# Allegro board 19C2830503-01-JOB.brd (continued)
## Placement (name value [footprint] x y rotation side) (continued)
U35  TI_SN74AVC4T245PWR  [SOIC_16P_26_197X252]  30.1 47.37 0 top
U36  TI_PCA9306DCUT  [SOIC_8P_20_79X122]  38.35 45.97 0 bottom
U37  TI_SN74AVC4T245PWR  [SOIC_16P_26_197X252]  35.81 47.35 0 top
U38  TI_TPS51200DRCT  [QFN10P_20_118X118_TP94X65V5]  105.54 46.61 90 top
U39  SAMSUNG_K4B4G1646B-HCK0  [BGA_96P_31_524X394_C14]  46.1 42.1 270 top
U40  SAMSUNG_K4B4G1646B-HCK0  [BGA_96P_31_524X394_C14]  57.78 42.1 270 top
U41  SAMSUNG_K4B4G1646B-HCK0  [BGA_96P_31_524X394_C14]  69.42 42.1 270 top
U42  SAMSUNG_K4B4G1646B-HCK0  [BGA_96P_31_524X394_C14]  81.15 42.1 270 top
U43  SAMSUNG_K4B4G1646B-HCK0  [BGA_96P_31_524X394_C14]  92.84 42.1 270 top
U44  TI_UCD74120RVF  [QFN40P20_276X197T209X130V21]  130.56 35.94 270 top
U45  TI_SN74LVC244APWR  [SOIC_20P_26_256X252]  146.81 171.96 90 bottom
U46  ATMEL_AT93C46DN-SH-T  [SOIC_8P_50_193X236]  154.18 165.1 180 bottom
U47  MICROCHIP_MCP23S17T-E/SS  [SOIC_28P_26_402X307]  100.2 163.58 90 bottom
U48  MICROCHIP_MCP23S17T-E/SS  [SOIC_28P_26_402X307]  90.42 163.58 90 bottom
U49  TI_TS3L301DGG  [SOIC_48P_20_492X319]  140.72 155.96 270 bottom
U50  MICROCHIP_MCP23S17T-E/SS  [SOIC_28P_26_402X307]  106.17 153.16 90 bottom
U51  TI_SN74AVC4T245PWR  [SOIC_16P_26_197X252]  159.64 144.53 0 bottom
U52  TI_TXS0108EPWR  [SOIC_20P_26_256X252]  151.51 144.53 0 bottom
U53  MICROCHIP_MCP23S17T-E/SS  [SOIC_28P_26_402X307]  98.3 128.91 90 bottom
U54  TI_PCA9517DR  [SOIC_8P_50_193X236]  79.32 124.84 0 bottom
U55  TI_SN74LVC2G157DCUT  [SOIC_8P_20_79X122]  78.61 113.41 90 top
U56  TI_MAX3221ECPWR  [SOIC_16P_26_197X252]  156.21 114.81 180 bottom
U57  TI_SN74AVC4T245PWR  [SOIC_16P_26_197X252]  80.9 113.54 0 bottom
U58  TI_PCA9517DR  [SOIC_8P_50_193X236]  129.41 106.3 90 bottom
U59  TI_TPS2065CDBVR  [SOT-23_5P]  156.34 105.79 270 bottom
U60  TI_TPS51200DRCT  [QFN10P_20_118X118_TP94X65V5]  36.7 38.61 270 bottom
U61  TI_REF5025AID  [SOIC_8P_50_193X236]  131.93 74.88 180 top
U62  TI_SN74LVC1G32DCK  [SC70_5P]  99.31 122.17 270 bottom
U63  TI_SN74AUCH16244DGGR  [SOIC_48P_20_492X319]  36.93 131.01 90 bottom
U64  TI_SN74AUCH16244DGGR  [SOIC_48P_20_492X319]  36.93 144.27 90 bottom
U65  TI_SN74AUCH245RGYR  [QFN_20P_20_177X138_TP]  43.43 130.68 90 top
U67  TI_SN74AUC1G125DCKR  [SC70_5P]  40.94 147.88 180 top
U68  TI_SN74AUCH245RGYR  [QFN_20P_20_177X138_TP]  43.43 136.78 90 top
U69  TI_SN74LVC1G04DBVR  [SOT-23_5P]  50.7 162.38 0 bottom
U70  TI_SN74LVC1G07DCKR  [SC70_5P]  158.65 102.24 0 bottom
Y1  12MHz_20pF  [XTAL_2P_161_205X134_H59]  162.81 158.62 180 top
Y2  16MHz  [XTAL_2P_152_197X126]  161.26 134.16 0 top
Y3  25MHz_20pF  [XTAL_2P_161_205X134_H59]  147.45 87.44 0 bottom
Y4  25MHz_20pF  [XTAL_2P_161_205X134_H59]  150.5 63.81 0 bottom

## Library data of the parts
AMC1 = 00_GF-AMC-B_0
ATT PWR = 160_SW_4P_TSVB_0
B1-B8 B16 B17 B20 B27 B30 B32-B34 B38 B41 B43 B45 B46 B48 PB1 = 1212_BEAD_0
B9-B15 B23 B25 B31 B39 B44 B47 = 1212_FILTER_NFW31SP106X1E4L_0
B22 B24 = 1212_FILTER_0
B28 B29 = 1212_FILTER_NFM21P_0
C1-C6 C13 C17 C19 C21 C22 C24 C25 C27 C29 C34-C37 C40 C44 C45 C49 C55 C62 C67 C86 C87 C89 C92 C94 C95 C101 C102 C107 C114 C115 C117 C126-C130 C132 C133 C135 C136 C138 C139 C141 C142 C146 C147 C149 C152 C153 C155-C159 C161 C162 C164 C166 C167 C170 C171 C174-C180 C183 C184 C187 C189-C191 C193 C198-C200 C203-C205 C208 C210 C211 C215 C216 C218 C219 C224 C225 C227 C229 C230 C233-C235 C237 C238 C240 C241 C243 C245 C247 C248 C253 C257-C259 C262 C265 C267 C270 C272 C274 C276 C277 C282 C287 C288 C291 C296 C300-C303 C307-C309 C311 C312 C316-C319 C321 C323-C325 C331 C332 C334 C337 C338 C340-C342 C345 C347 C352-C356 C360-C362 C364 C366 C367 C371 C374 C378 C379 C382-C384 C388 C389 C392-C396 C398 C401 C402 C414 C416-C418 C421 C424 C427 C430 C434 C438-C440 C442-C450 C454-C457 C459 C460 C462-C475 C477-C483 C485-C496 C499-C502 C505-C507 C510-C513 C517 C521 C523 C525 C531 C538 C543 C555 C560 C561 C564 C566-C568 C571 C574 C577 C579 C580 C582 C588-C590 C592 C594 C596 C599 C601 C609 C613 C616 C619 C623 C626 C627 C630 C632 C636 C637 C641 C643 C646-C648 C658 C659 C661 C666 C668 C670-C672 C674 C675 C677 C679 C681 C682 C684 C686-C689 C695 C700 C702 C703 C710 C712 C715-C717 C720 C723 C725 C726 C730 C732 C734-C755 C758-C760 C763 C768-C772 C774 C776 C777 C782 C783 C788 C790 C793 = 11_C_0: signal model: DEFAULT_CAPACITOR_100000pF_2_1
C7 C8 C11 C12 C15 C23 C30 C31 C108 C113 C143 C144 C148 C150 C151 C169 C207 C249 C315 C333 C336 C339 C343 C346 C349 C372 C376 C385 C386 C397 C413 C578 C591 C654 C669 C778 C787 = 11_C_0: signal model: DEFAULT_CAPACITOR_1e+07pF_2_1
C9 = 11_C_0: signal model: DEFAULT_CAPACITOR_1200pF_2_1
C10 C16 C20 C26 C54 C69 C72 C73 C77 C78 C80 C85 C90 C99 C120-C122 C131 C192 C195 C201 C202 C206 C209 C214 C217 C220 C246 C255 C260 C263 C268 C273 C278 C290 C294 C363 C391 C514 C520 C522 C526 C527 C529 C542 C545-C547 C549 C550 C558 C559 C565 C572 C581 C584 C585 C602 C603 C606-C608 C610-C612 C615 C620 C622 C628 C631 C635 C639 C640 C644 C650-C653 C662 C663 C667 C673 C676 C678 C685 C698 C701 C705 C707 C709 C713 C714 C756 C757 C761 C764 C766 C784 C794 = 11_C_0: signal model: DEFAULT_CAPACITOR_10000pF_2_1
C14 = 11_C_0: signal model: DEFAULT_CAPACITOR_8200pF_2_1
C18 C81-C84 C116 C236 C239 C244 C252 C350 C461 C515 C516 C518 C519 C530 C533 C535 C539-C541 C548 C552-C554 C556 C562 C563 C573 C575 C583 C586 C587 C597 C598 C600 C604 C605 C617 C621 C624 C629 C633 C634 C638 C645 C649 C655 C657 C660 C664 C665 C680 C683 C690-C694 C696 C697 C699 C704 C706 C711 = 11_C_0: signal model: DEFAULT_CAPACITOR_560pF_2_1
C28 C33 = 11_C_0: signal model: DEFAULT_CAPACITOR_33pF_2_1
C32 = 11_C_0: signal model: DEFAULT_CAPACITOR_8.2pF_2_1
C38 C42 C100 C160 C228 C344 C415 C625 C733 C792 = 11_C_0: signal model: DEFAULT_CAPACITOR_2.2e+06pF_2_1
C39 C831-C834 = 11_C_POLAR_0
C41 C173 = 11_C_POLAR_0: signal model: DEFAULT_CAPACITOR_1e+08pF_2_1
C43 C48 C242 C256 C264 C289 C299 C306 C381 C425 C426 C504 C537 C780 C781 C785 C786 C789 = 11_C_0: signal model: DEFAULT_CAPACITOR_2.2e+07pF_2_1
C46 C47 C52 C53 C56 C59 C64 C68 C97 C98 C110 C111 C196 C197 C222 C223 C313 C365 C373 C377 C419 C422 C451 C452 C509 C576 C595 C614 C656 C721 C762 C773 C779 = 11_C_0: signal model: DEFAULT_CAPACITOR_4.7e+07pF_2_1
C50 C51 C60 C63 C182 C221 C292 C791 = 11_C_0: signal model: DEFAULT_CAPACITOR_220000pF_2_1
C57 C76 C104 C105 C185 C188 C194 C212 C213 C226 C254 C261 C271 C293 C295 C297 C328 C409 C420 C429 C441 C508 C557 C593 C618 C767 = 11_C_0: signal model: DEFAULT_CAPACITOR_4.7e+06pF_2_1
C58 C79 C109 C186 C269 C279-C281 C348 C370 C453 C458 C528 C536 C708 C722 = 11_C_0: signal model: DEFAULT_CAPACITOR_1000pF_2_1
C61 C74 C88 C91 C93 C96 C103 C106 C134 C137 C165 C168 C181 C232 C250 C266 C275 C285 C304 C305 C314 C322 C329 C330 C335 C351 C357-C359 C410-C412 C423 C476 C484 C724 C729 C731 C775 = 11_C_0: signal model: DEFAULT_CAPACITOR_1e+06pF_2_1
C65 C75 C327 C380 C432 C435-C437 C503 C544 C728 C795 = 11_C_POLAR_0: signal model: DEFAULT_CAPACITOR_4.7e+08pF_2_1
C66 C326 C368 C390 C399 C400 C433 C498 C532 C551 C642 C727 C765 = 11_C_0: signal model: DEFAULT_CAPACITOR_1e+08pF_2_1
C70 C71 = 11_C_0: signal model: DEFAULT_CAPACITOR_10pF_2_1
C112 C140 C163 C497 = 11_C_0: signal model: DEFAULT_CAPACITOR_100pF_2_1
C118 = 11_C_0: signal model: DEFAULT_CAPACITOR_470pF_2_1
C119 C124 C125 C145 C231 C251 C283 C284 C524 C534 = 11_C_0: signal model: 11_C_0_C0402_DISCRETE_NL/0.1UF_NL/0.1uF
C123 C172 = 11_C_0: signal model: DEFAULT_CAPACITOR_22000pF_2_1
C369 C403 C796-C823 C825-C830 C835-C844 = 11_C_0
C375 = 11_C_0: signal model: DEFAULT_CAPACITOR_1.5pF_2_1
C387 = 11_C_0: signal model: DEFAULT_CAPACITOR_56pF_2_1
C404-C408 = 11_C_0: signal model: DEFAULT_CAPACITOR_470000pF_2_1
C428 C431 = 11_C_POLAR_0: signal model: DEFAULT_CAPACITOR_4.7e+07pF_2_1
C569 C570 C718 C719 = 11_C_0: signal model: DEFAULT_CAPACITOR_27pF_2_1
CN1 = 1654_PWR_2P_5223957-3_0
CN2 CN8 = 1653_JH3X1V-2M_0
CN3 = 1654_BB_60X2P_4HOLD_QSH_0
CN4-CN6 CN10 CN23 = 1654_HS_UFL-R-SMT-1_0
CN7 = 1653_JH6X1V-2M_0
CN9 CN15 CN24 = 1653_HD_2P_D_0
CN11-CN13 = 1654_COAXIAL_4P_MM8030_0
CN16 = 1652_RJ45_28P_RTB-19GB9J1A_0
CN17 = 1653_JH4X2V_0
CN18 = 1654_RF-SMAC037_0
CN19 CN20 = 1653_HD_4X1P_222-96_0
CN21 = 1653_JH3X1V-51462803_0
CN22 = 1653_HD_5X2P_0
D1 = 130_TVS_SON6_TPD4S012DRY_0
D3 = 130_LED_2P_R_KPA-1606EC_0
D4 = 130_LED_LED-0603_G_0
D5 DBG_D2 DBG_D3 = 130_LED_2P_B_KPA-1606QBC-D_0
D6 = 130_LED_LED-0603_R_0
D7 = 130_SCHOTTKY_0
D8 = 130_ZENER_SOT-23A_13_1
D9 D11 = 130_SCHOTTKY_ANODE2_0
D10 = 130_SCHOTTKY_0805_0
D14 = 130_TVS_SOT_TPD2EUSB30DRT_0
DBG_D1 = 130_LED_3P_KPBA-3010ESGC_0
DC_IN1 = 12_DCJACK_3P_2DC-0005B100_0
DIMM1 = 1651_DDR3-SODIMM_204P_DDRSK_E_0
EEPROM1 = 141_ST_M24M01-HRMN6TP_0
EMU1 = 1654_BB_30X2P_2HOLD_QSH_0
ESD1 = 00_AMC-ESD-B_0
FAN1 = 12_WF_4P_BOX_D_0
FM1-FM4 = 00_Fiducial_0
FTDI_USB = 1654_USB-UH51543_MABTYPE_0
GPS1 = 141_GNS_TC6000G_1
H1 H2 = 00_H35P7-MTH_0
H7 = 00_SCREWHOLE_OVAL_NPTH_0
H8 = 00_H27P35-MTH_0
J1 = 1654_ATCA_160P_J30_1
J2 = 1654_ATCA_160P_J31_1
L1 = 1211_L_0: signal model: DEFAULT_INDUCTOR_22000nH_2_1
L2 L8 = 1211_CHOKE_0: signal model: DEFAULT_INDUCTOR_3300nH_2_1
L3 L5-L7 L12 = 1211_CHOKE_0: signal model: DEFAULT_INDUCTOR_470nH_2_1
L4 = 1211_CHOKE_0: signal model: DEFAULT_INDUCTOR_200nH_2_1
L9 = 1211_L_0: signal model: DEFAULT_INDUCTOR_1800nH_2_1
L10 = 09_L_0: signal model: DEFAULT_INDUCTOR_82nH_2_1
L11 = 1211_L_0: signal model: DEFAULT_INDUCTOR_3.6nH_2_1
LCD1 = 968_LCD_17P_NHD-C12832A1Z_0
MCU SOC = 12_WF_4P_D_744-81-04TW20_0
NAND1 = 141_MICRON_MT29F4G08ABBDAHCIT_0
NOR1 = 141_NUMONYX_N25Q128A11BSF40F_0
OSC1 OSC4 = 1233_OSC_4P_0
OSC2 = 1233_OSC_6P_0
OSC3 = 1233_OSC_4P_M6049LF_0
PHY1 PHY2 = 141_MARVELL_88E1111-B1-BAB_0
PMBUS1 = 1653_JH5X1V_0
Q1 Q7 Q8 = 141_TI_TPS73701DRBT_0
Q2 = 141_TI_TPS74701_0
Q3-Q5 Q9 Q11 Q12 Q14 Q16 Q18 = 131_SOT-23A_BEC_0
Q6 Q15 Q17 Q21 = 141_MICROCHIP_MCP9700AT-E-LT_0
Q10 = 131_REG_SOT-223_TLV1117_0
Q13 = 131_REG_SOT-23_APL431LBAI_0
Q19 = 131_SOIC8_SGDP_0
Q20 = 131_N_MOS_SOT-23_1
R1 R2 = 10_R_0: signal model: DEFAULT_RESISTOR_0.01OHM_2_1
R3 R65 R77 R198 R216 R261 R267 R320 R328 R346 R397 R419 R435 R441 R442 R472 R567 R769 R770 R783 = 10_R_0: signal model: DEFAULT_RESISTOR_1000OHM_2_1
R4 R7 R11 R14 R20 R21 R24 R28 R40 R59 R81-R83 R92 R93 R121 R122 R174-R176 R214 R222 R228 R248 R249 R251 R255 R270 R274 R275 R281 R292 R297 R300 R304 R306 R307 R318 R321 R329 R377 R386 R395 R404-R407 R411-R418 R422 R429 R430 R446-R453 R460 R461 R479 R484 R495-R498 R505 R528 R540 R544 R546 R581 R603 R604 R610 R612 R616 R617 R623 R639 R652 R679 R735 R750 R762 R773 R780 R785 R787 R791 R793 = 10_R_0: signal model: DEFAULT_RESISTOR_10000OHM_2_1
R5 R6 R147-R150 R171 R196 R237 R260 R276 R279 R287 R308 R319 R322 R326 R343 R347 R365 R410 R432 R487-R489 R502 R503 R549 R568 R585 R601 R643 R677 R686 R687 R726 R798-R817 = 10_R_0
R8 = 10_R_0: signal model: DEFAULT_RESISTOR_82500OHM_2_1
R9 R18 R26 R35 R39 R41 R45 R46 R51 R52 R54 R75 R86 R98 R116 R117 R123 R129-R131 R145 R162-R166 R178-R185 R188-R190 R192 R193 R200 R203 R204 R206 R210 R215 R223 R225 R226 R231 R234 R235 R238 R242-R247 R250 R252 R253 R262-R265 R268 R269 R277 R280 R285 R301 R305 R323 R325 R338 R351 R354 R378 R380 R433 R468 R471 R514 R515 R524 R531 R536 R541 R547 R555 R560 R563 R564 R566 R579 R580 R589 R607 R608 R613 R622 R642 R644-R647 R653-R655 R658 R660 R669 R725 R727-R730 R736-R738 R742 R755 R759 R764 R774 = 10_R_0: signal model: DEFAULT_RESISTOR_0.001OHM_2_1
R10 = 10_R_0: signal model: DEFAULT_RESISTOR_1870OHM_2_1
R12 R27 R100 R309 R369 R372 R373 R423 R480 R490 R609 R621 R628 R690-R692 = 10_R_0: signal model: DEFAULT_RESISTOR_22OHM_2_1
R13 = 10_R_0: signal model: DEFAULT_RESISTOR_31600OHM_2_1
R15 = 10_R_0: signal model: DEFAULT_RESISTOR_56200OHM_2_1
R16 R25 R29 R34 R36 R38 R42 R48 R50 R56 R69 R220 R224 R232 R271 R289-R291 R312 R313 R324 R330-R332 R334 R336 R337 R339-R341 R344 R359 R362 R363 R366 R379 R381 R385 R389 R390 R394 R408 R421 R425 R426 R428 R438 R439 R470 R477 R521 R530 R557 R569-R573 R575-R578 R587 R590-R600 R620 R625 R629 R631 R648 R650 R651 R661-R666 R672-R676 R688 R696 R701 R702 R706 R707 R709 R711 R713 R714 R720 R721 R723 R731 R733 R734 R739 R744-R749 R751-R754 R758 R796 R797 = 10_R_0: signal model: DEFAULT_RESISTOR_4700OHM_2_1
R17 R105 R128 R456 R699 = 10_R_0: signal model: DEFAULT_RESISTOR_22600OHM_2_1
R19 = 10_R_0: signal model: DEFAULT_RESISTOR_17400OHM_2_1
R22 = 10_R_0: signal model: DEFAULT_RESISTOR_1690OHM_2_1
R23 = 10_R_0: signal model: DEFAULT_RESISTOR_3570OHM_2_1
R30 R70 R111 R492 R534 = 10_R_0: signal model: DEFAULT_RESISTOR_330OHM_2_1
R31 R76 R219 R299 R494 R504 R510 R522 R525 R533 = 10_R_0: signal model: DEFAULT_RESISTOR_510OHM_2_1
R32 R239 R240 R256 R257 R272 R273 R618 R624 R626 R630 R633 R636 R637 R641 R680 R681 R689 R695 R700 R705 R710 R717 = 10_R_0: signal model: DEFAULT_RESISTOR_49.9OHM_2_1
R33 R91 R146 R152 R170 R195 R201 R229 R233 R282 R288 R295 R370 R473-R476 R682 R683 R693 = 10_R_0: signal model: DEFAULT_RESISTOR_100OHM_2_1
R37 R43 R44 R47 R49 R53 R55 R57 R60 R62-R64 R66-R68 R71-R73 R78-R80 R87 R89 R90 R94 R96 R97 R103 R104 R109 R110 R157 R158 R293 R294 R311 R314-R316 R348 R352 R355 R357 R364 R367 R368 R374 R383 R384 R387 R388 R391 R393 R396 R398 R401 R402 R507 R516 R520 R523 R527 R529 R532 R535 R539 R542 R558 R605 R606 R614 R615 R619 R668 R670 R697 R703 R708 R712 R718 R722 R724 R732 R740 R741 R743 R756 R757 = 10_R_0: signal model: DEFAULT_RESISTOR_10OHM_2_1
R58 R61 R112 R511 R517 R519 = 10_R_0: signal model: DEFAULT_RESISTOR_4750OHM_2_1
R84 R161 R217 = 10_R_0: signal model: DEFAULT_RESISTOR_8200OHM_2_1
R85 R106 R173 R191 R197 R358 R399 R400 R420 R424 R469 R582 R583 = 10_R_0: signal model: DEFAULT_RESISTOR_2000OHM_2_1
R113 R136 R768 = 10_R_0: signal model: DEFAULT_RESISTOR_8060OHM_2_1
R114 R115 R134 R135 R766 R767 = 10_R_0: signal model: DEFAULT_RESISTOR_2490OHM_2_1
R137-R140 R342 R345 R349 R356 = 10_R_0: signal model: DEFAULT_RESISTOR_750OHM_2_1
R151 R172 R317 R403 R409 R427 R431 R434 R436 R437 R440 R586 R611 = 10_R_0: signal model: DEFAULT_RESISTOR_100000OHM_2_1
R159 R202 R588 R602 R627 R634 R659 R678 R694 R704 R715 = 10_R_0: signal model: DEFAULT_RESISTOR_4990OHM_2_1
R207 R213 = 10_R_0: signal model: DEFAULT_RESISTOR_1OHM_2_1
R208 R375 = 10_R_0: signal model: DEFAULT_RESISTOR_10200OHM_2_1
R209 R376 = 10_R_0: signal model: DEFAULT_RESISTOR_1500OHM_2_1
R212 R218 = 10_R_0: signal model: DEFAULT_RESISTOR_90900OHM_2_1
R221 R227 = 10_R_0: signal model: DEFAULT_RESISTOR_560OHM_2_1
R241 R259 R303 = 10_R_0: signal model: DEFAULT_RESISTOR_3160OHM_2_1
R258 R302 R584 = 10_R_0: signal model: DEFAULT_RESISTOR_5600OHM_2_1
R278 R286 R574 = 10_R_0: signal model: DEFAULT_RESISTOR_33OHM_2_1
R283 = 10_R_0: signal model: DEFAULT_RESISTOR_39200OHM_2_1
R284 = 10_R_0: signal model: DEFAULT_RESISTOR_36500OHM_2_1
R296 R538 R551 R761 = 10_R_0: signal model: DEFAULT_RESISTOR_1300OHM_2_1
R298 = 10_R_0: signal model: DEFAULT_RESISTOR_475OHM_2_1
R310 R632 R635 R638 R649 R656 R667 R671 R685 R698 = 10_R_0: signal model: DEFAULT_RESISTOR_3000OHM_2_1
R327 R333 R335 R350 R371 R382 = 10_R_0: signal model: DEFAULT_RESISTOR_220OHM_2_1
R353 = 10_R_0: signal model: DEFAULT_RESISTOR_698OHM_2_1
R360 R361 = 10_R_0: signal model: DEFAULT_RESISTOR_75000OHM_2_1
R443-R445 R454 R455 R457 R458 R462-R467 R763 R765 R772 R775 R779 R781 R782 R786 R788-R790 R792 R794 R795 = 10_R_0: signal model: DEFAULT_RESISTOR_39.2OHM_2_1
R459 R537 R550 = 10_R_0: signal model: DEFAULT_RESISTOR_2OHM_2_1
R481 = 10_R_0: signal model: DEFAULT_RESISTOR_2870OHM_2_1
R482 = 10_R_0: signal model: DEFAULT_RESISTOR_2200OHM_2_1
R483 = 10_R_0: signal model: DEFAULT_RESISTOR_12100OHM_2_1
R485 R491 R493 R506 R513 = 10_R_0: signal model: DEFAULT_RESISTOR_27OHM_2_1
R499-R501 = 10_R_0: signal model: DEFAULT_RESISTOR_3300OHM_2_1
R508 = 10_R_0: signal model: DEFAULT_RESISTOR_6980OHM_2_1
R509 = 10_R_0: signal model: DEFAULT_RESISTOR_12OHM_2_1
R512 = 10_R_0: signal model: DEFAULT_RESISTOR_200OHM_2_1
R518 R526 = 10_R_0: signal model: DEFAULT_RESISTOR_33000OHM_2_1
R545 R553 R760 = 10_R_0: signal model: DEFAULT_RESISTOR_931OHM_2_1
R640 R684 R719 R771 R776-R778 R784 RR1 = 10_R_0: signal model: DEFAULT_RESISTOR_240OHM_2_1
R657 R716 = 10_R_0: signal model: DEFAULT_RESISTOR_45.3OHM_2_1
RST_MCU1 = 160_SW_2P_PT-004-E1_0
SIM1 = 1654_SIMCARD_8P_FMS006Z-2001_0
SOC_USB = 1654_USB3-A_9P_UEA1112C-4HK1_0
SOCKET1 = 00_TI_SOC_K2H_Socket_0
SW1 = 160_SW_8P_ESD104EZ_0
TP1 TP6 TP10 TP59 = 00_TP-S40_0
TP2-TP5 TP7-TP9 TP11-TP58 TP60-TP62 TP64-TP97 = 00_TP28_0
U1 U2 = 141_TI_TPS54620RGY_0
U3 = 141_FTDI_FT2232HL_0
U4 U28 = 14S_SN74LVC2G125DCUR_US-8_1
U5 U52 = 141_TI_TXS0108EPWR_0
U6 = 141_TI_SN74AHCT1G08DCKT_0
U7 = 14_TI_LM3S2D93-IQC80_0
U8 = 141_TI_UCD74111_0
U9 U23 = 141_TI_UCD7242RSJT_0
U10 U44 = 141_TI_UCD74120_0
U11 U62 = 141_TI_SN74LVC1G32_0
U12 U17 U21 U30 U55 = 141_TI_SN74LVC2G157_0
U13 = 141_TI_UCD9090_0
U14 U15 U19 = 141_TI_CDCM6208_1
U16 U25 = 141_TI_UCD9244RGCR_1
U18 U56 = 141_TI_MAX3221E_0
U20 = 141_IDT_5V41068A_0
U22 U34 U54 U58 = 141_TI_PCA9517DR_0
U24 = 14_TI_TMS320TCI6638_4
U26 = 141_TI_SN74LVC1G19DCKR_0
U27 = 141_TI_UCD74106_0
U29 = 141_TI_DAC8550_0
U31 U36 = 141_TI_PCA9306DCUT_0
U32 U35 U37 U51 U57 = 141_TI_SN74AVC4T245PWR_0
U33 = 141_TI_TXS4555RGTR_0
U38 U60 = 141_TI_TPS51200DRCT_0
U39-U43 = 141_SAMSUNG_K4B4G1646B-HCK0_0
U45 = 14S_74LVC244_TSSOP20-S_1
U46 = 141_ATMEL_AT93C46DN-SH-T_0
U47 U48 U50 U53 = 141_MCP23S17T_SSOP28-209MIL_0
U49 = 141_TI_TS3L301DGG_1
U59 = 141_TI_TPS2065CDBVR_1
U61 = 141_TI_REF5050AIDR_0
U63 U64 = 141_SN74AUCH16244DGGR_TSSOP48_0
U65 U68 = 141_TI_SN74AUCH245RGYR_0
U67 = 141_TI_SN74AUC1G125DCKR_0
U69 = 141_TI_SN74LVC1G04DBVR_0
U70 = 141_TI_SN74LVC1G07DCKR_0
Y1-Y4 = 1231_XTAL_2P_0

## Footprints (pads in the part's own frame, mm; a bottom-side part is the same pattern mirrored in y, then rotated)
ACM2012
  rect 0.762x0.406 smd: 1(-0.925,0.4) 2(-0.925,-0.4) 3(0.925,-0.4) 4(0.925,0.4)
AMC-ESD-B
  custom 1.175x1.175 smd: 1(0,-0.3)
  custom 0.25x0.25 smd: 2(-125.5,1.55) 3(-138.5,1.55)
  round 3.2 hole 2.692: 4(0,0)
ATCA_160P_384312
  rect 0.864x0.864 hole 0.457: A1(11.25,1.1)
  round 0.864 hole 0.457: A2(8.75,1.1) A3(6.25,1.1) A4(3.75,1.1) A5(1.25,1.1) A6(-1.25,1.1) A7(-3.75,1.1) A8(-6.25,1.1) A9(-8.75,1.1) A10(-11.25,1.1) B1(11.25,2.3) B2(8.75,2.3) B3(6.25,2.3) B4(3.75,2.3) B5(1.25,2.3) B6(-1.25,2.3) B7(-3.75,2.3) B8(-6.25,2.3) B9(-8.75,2.3) B10(-11.25,2.3) C1(11.25,5.6) C2(8.75,5.6) C3(6.25,5.6) C4(3.75,5.6) C5(1.25,5.6) C6(-1.25,5.6) C7(-3.75,5.6) C8(-6.25,5.6) C9(-8.75,5.6) C10(-11.25,5.6) D1(11.25,6.8) D2(8.75,6.8) D3(6.25,6.8) D4(3.75,6.8) D5(1.25,6.8) D6(-1.25,6.8) D7(-3.75,6.8) D8(-6.25,6.8) D9(-8.75,6.8) D10(-11.25,6.8) E1(11.25,10.1) E2(8.75,10.1) E3(6.25,10.1) E4(3.75,10.1) E5(1.25,10.1) E6(-1.25,10.1) E7(-3.75,10.1) E8(-6.25,10.1) E9(-8.75,10.1) E10(-11.25,10.1) F1(11.25,11.3) F2(8.75,11.3) F3(6.25,11.3) F4(3.75,11.3) F5(1.25,11.3) F6(-1.25,11.3) F7(-3.75,11.3) F8(-6.25,11.3) F9(-8.75,11.3) F10(-11.25,11.3) G1(11.25,14.6) G2(8.75,14.6) G3(6.25,14.6) G4(3.75,14.6) G5(1.25,14.6) G6(-1.25,14.6) G7(-3.75,14.6) G8(-6.25,14.6) G9(-8.75,14.6) G10(-11.25,14.6) GA1(10.21,0) GA2(7.71,0) GA3(5.21,0) GA4(2.71,0) GA5(0.21,0) GA6(-2.29,0) GA7(-4.79,0) GA8(-7.29,0) GA9(-9.79,0) GA10(-12.29,0) GH1(11.25,17) GH2(8.75,17) GH3(6.25,17) GH4(3.75,17) GH5(1.25,17) GH6(-1.25,17) GH7(-3.75,17) GH8(-6.25,17) GH9(-8.75,17) GH10(-11.25,17) H1(11.25,15.8) H2(8.75,15.8) H3(6.25,15.8) H4(3.75,15.8) H5(1.25,15.8) H6(-1.25,15.8) H7(-3.75,15.8) H8(-6.25,15.8) H9(-8.75,15.8) H10(-11.25,15.8)
  round 0.711 hole 0.457: GB1(11.25,3.5) GB2(8.75,3.5) GB3(6.25,3.5) GB4(3.75,3.5) GB5(1.25,3.5) GB6(-1.25,3.5) GB7(-3.75,3.5) GB8(-6.25,3.5) GB9(-8.75,3.5) GB10(-11.25,3.5) GC1(11.25,4.4) GC2(8.75,4.4) GC3(6.25,4.4) GC4(3.75,4.4) GC5(1.25,4.4) GC6(-1.25,4.4) GC7(-3.75,4.4) GC8(-6.25,4.4) GC9(-8.75,4.4) GC10(-11.25,4.4) GD1(11.25,8) GD2(8.75,8) GD3(6.25,8) GD4(3.75,8) GD5(1.25,8) GD6(-1.25,8) GD7(-3.75,8) GD8(-6.25,8) GD9(-8.75,8) GD10(-11.25,8) GE1(11.25,8.9) GE2(8.75,8.9) GE3(6.25,8.9) GE4(3.75,8.9) GE5(1.25,8.9) GE6(-1.25,8.9) GE7(-3.75,8.9) GE8(-6.25,8.9) GE9(-8.75,8.9) GE10(-11.25,8.9) GF1(11.25,12.5) GF2(8.75,12.5) GF3(6.25,12.5) GF4(3.75,12.5) GF5(1.25,12.5) GF6(-1.25,12.5) GF7(-3.75,12.5) GF8(-6.25,12.5) GF9(-8.75,12.5) GF10(-11.25,12.5) GG1(11.25,13.4) GG2(8.75,13.4) GG3(6.25,13.4) GG4(3.75,13.4) GG5(1.25,13.4) GG6(-1.25,13.4) GG7(-3.75,13.4) GG8(-6.25,13.4) GG9(-8.75,13.4) GG10(-11.25,13.4)
BB_30X2P_20_838X285_F
  round 1.016 hole 1.016 unplated: (-10.065,2.67) (10.065,2.67)
  oval 0.279x2.286 smd: 1(-7.25,-2.87) 2(-7.25,2.87) 3(-6.75,-2.87) 4(-6.75,2.87) 5(-6.25,-2.87) 6(-6.25,2.87) 7(-5.75,-2.87) 8(-5.75,2.87) 9(-5.25,-2.87) 10(-5.25,2.87) 11(-4.75,-2.87) 12(-4.75,2.87) 13(-4.25,-2.87) 14(-4.25,2.87) 15(-3.75,-2.87) 16(-3.75,2.87) 17(-3.25,-2.87) 18(-3.25,2.87) 19(-2.75,-2.87) 20(-2.75,2.87) 21(-2.25,-2.87) 22(-2.25,2.87) 23(-1.75,-2.87) 24(-1.75,2.87) 25(-1.25,-2.87) 26(-1.25,2.87) 27(-0.75,-2.87) 28(-0.75,2.87) 29(-0.25,-2.87) 30(-0.25,2.87) 31(0.25,-2.87) 32(0.25,2.87) 33(0.75,-2.87) 34(0.75,2.87) 35(1.25,-2.87) 36(1.25,2.87) 37(1.75,-2.87) 38(1.75,2.87) 39(2.25,-2.87) 40(2.25,2.87) 41(2.75,-2.87) 42(2.75,2.87) 43(3.25,-2.87) 44(3.25,2.87) 45(3.75,-2.87) 46(3.75,2.87) 47(4.25,-2.87) 48(4.25,2.87) 49(4.75,-2.87) 50(4.75,2.87) 51(5.25,-2.87) 52(5.25,2.87) 53(5.75,-2.87) 54(5.75,2.87) 55(6.25,-2.87) 56(6.25,2.87) 57(6.75,-2.87) 58(6.75,2.87) 59(7.25,-2.87) 60(7.25,2.87)
  rect 4.699x0.635 smd: H3(-3.175,0) H4(3.175,0)
  rect 2.54x0.635 smd: H5(8.065,0) H6(-8.065,0)
BB_60X2P_20_2225X285_F
  round 1.016 hole 1.016 unplated: (-20.065,2.67) (20.065,2.67)
  oval 0.279x2.286 smd: 1(-17.25,-2.87) 2(-17.25,2.87) 3(-16.75,-2.87) 4(-16.75,2.87) 5(-16.25,-2.87) 6(-16.25,2.87) 7(-15.75,-2.87) 8(-15.75,2.87) 9(-15.25,-2.87) 10(-15.25,2.87) 11(-14.75,-2.87) 12(-14.75,2.87) 13(-14.25,-2.87) 14(-14.25,2.87) 15(-13.75,-2.87) 16(-13.75,2.87) 17(-13.25,-2.87) 18(-13.25,2.87) 19(-12.75,-2.87) 20(-12.75,2.87) 21(-12.25,-2.87) 22(-12.25,2.87) 23(-11.75,-2.87) 24(-11.75,2.87) 25(-11.25,-2.87) 26(-11.25,2.87) 27(-10.75,-2.87) 28(-10.75,2.87) 29(-10.25,-2.87) 30(-10.25,2.87) 31(-9.75,-2.87) 32(-9.75,2.87) 33(-9.25,-2.87) 34(-9.25,2.87) 35(-8.75,-2.87) 36(-8.75,2.87) 37(-8.25,-2.87) 38(-8.25,2.87) 39(-7.75,-2.87) 40(-7.75,2.87) 41(-7.25,-2.87) 42(-7.25,2.87) 43(-6.75,-2.87) 44(-6.75,2.87) 45(-6.25,-2.87) 46(-6.25,2.87) 47(-5.75,-2.87) 48(-5.75,2.87) 49(-5.25,-2.87) 50(-5.25,2.87) 51(-4.75,-2.87) 52(-4.75,2.87) 53(-4.25,-2.87) 54(-4.25,2.87) 55(-3.75,-2.87) 56(-3.75,2.87) 57(-3.25,-2.87) 58(-3.25,2.87) 59(-2.75,-2.87) 60(-2.75,2.87) 61(2.75,-2.87) 62(2.75,2.87) 63(3.25,-2.87) 64(3.25,2.87) 65(3.75,-2.87) 66(3.75,2.87) 67(4.25,-2.87) 68(4.25,2.87) 69(4.75,-2.87) 70(4.75,2.87) 71(5.25,-2.87) 72(5.25,2.87) 73(5.75,-2.87) 74(5.75,2.87) 75(6.25,-2.87) 76(6.25,2.87) 77(6.75,-2.87) 78(6.75,2.87) 79(7.25,-2.87) 80(7.25,2.87) 81(7.75,-2.87) 82(7.75,2.87) 83(8.25,-2.87) 84(8.25,2.87) 85(8.75,-2.87) 86(8.75,2.87) 87(9.25,-2.87) 88(9.25,2.87) 89(9.75,-2.87) 90(9.75,2.87) 91(10.25,-2.87) 92(10.25,2.87) 93(10.75,-2.87) 94(10.75,2.87) 95(11.25,-2.87) 96(11.25,2.87) 97(11.75,-2.87) 98(11.75,2.87) 99(12.25,-2.87) 100(12.25,2.87) 101(12.75,-2.87) 102(12.75,2.87) 103(13.25,-2.87) 104(13.25,2.87) 105(13.75,-2.87) 106(13.75,2.87) 107(14.25,-2.87) 108(14.25,2.87) 109(14.75,-2.87) 110(14.75,2.87) 111(15.25,-2.87) 112(15.25,2.87) 113(15.75,-2.87) 114(15.75,2.87) 115(16.25,-2.87) 116(16.25,2.87) 117(16.75,-2.87) 118(16.75,2.87) 119(17.25,-2.87) 120(17.25,2.87)
  rect 4.699x0.635 smd: H3(-13.175,0) H4(-6.825,0) H7(6.825,0) H8(13.175,0)
  rect 2.54x0.635 smd: H5(-1.935,0) H6(-18.065,0) H9(18.065,0) H10(1.935,0)
  round 6.35 hole 3.962: H11(-24.33,0) H12(24.33,0)
BGA_36P_60_394X366
  round 0.508 smd: A1(-3.75,-3.75) A2(-2.25,-3.75) A3(-0.75,-3.75) A4(0.75,-3.75) A5(2.25,-3.75) A6(3.75,-3.75) B1(-3.75,-2.25) B2(-2.25,-2.25) B3(-0.75,-2.25) B4(0.75,-2.25) B5(2.25,-2.25) B6(3.75,-2.25) C1(-3.75,-0.75) C2(-2.25,-0.75) C3(-0.75,-0.75) C4(0.75,-0.75) C5(2.25,-0.75) C6(3.75,-0.75) D1(-3.75,0.75) D2(-2.25,0.75) D3(-0.75,0.75) D4(0.75,0.75) D5(2.25,0.75) D6(3.75,0.75) E1(-3.75,2.25) E2(-2.25,2.25) E3(-0.75,2.25) E4(0.75,2.25) E5(2.25,2.25) E6(3.75,2.25) F1(-3.75,3.75) F2(-2.25,3.75) F3(-0.75,3.75) F4(0.75,3.75) F5(2.25,3.75) F6(3.75,3.75)
BGA_63P_31_512X413_C14
  round 0.356 smd: A1(-4.4,-3.6) A2(-4.4,-2.8) A9(-4.4,2.8) A10(-4.4,3.6) B1(-3.6,-3.6) B9(-3.6,2.8) B10(-3.6,3.6) C3(-2.8,-2) C4(-2.8,-1.2) C5(-2.8,-0.4) C6(-2.8,0.4) C7(-2.8,1.2) C8(-2.8,2) D3(-2,-2) D4(-2,-1.2) D5(-2,-0.4) D6(-2,0.4) D7(-2,1.2) D8(-2,2) E3(-1.2,-2) E4(-1.2,-1.2) E5(-1.2,-0.4) E6(-1.2,0.4) E7(-1.2,1.2) E8(-1.2,2) F3(-0.4,-2) F4(-0.4,-1.2) F5(-0.4,-0.4) F6(-0.4,0.4) F7(-0.4,1.2) F8(-0.4,2) G3(0.4,-2) G4(0.4,-1.2) G5(0.4,-0.4) G6(0.4,0.4) G7(0.4,1.2) G8(0.4,2) H3(1.2,-2) H4(1.2,-1.2) H5(1.2,-0.4) H6(1.2,0.4) H7(1.2,1.2) H8(1.2,2) J3(2,-2) J4(2,-1.2) J5(2,-0.4) J6(2,0.4) J7(2,1.2) J8(2,2) K3(2.8,-2) K4(2.8,-1.2) K5(2.8,-0.4) K6(2.8,0.4) K7(2.8,1.2) K8(2.8,2) L1(3.6,-3.6) L2(3.6,-2.8) L9(3.6,2.8) L10(3.6,3.6) M1(4.4,-3.6) M2(4.4,-2.8) M9(4.4,2.8) M10(4.4,3.6)
BGA_96P_31_524X394_C14
  round 0.356 smd: A1(-6,-3.2) A2(-6,-2.4) A3(-6,-1.6) A7(-6,1.6) A8(-6,2.4) A9(-6,3.2) B1(-5.2,-3.2) B2(-5.2,-2.4) B3(-5.2,-1.6) B7(-5.2,1.6) B8(-5.2,2.4) B9(-5.2,3.2) C1(-4.4,-3.2) C2(-4.4,-2.4) C3(-4.4,-1.6) C7(-4.4,1.6) C8(-4.4,2.4) C9(-4.4,3.2) D1(-3.6,-3.2) D2(-3.6,-2.4) D3(-3.6,-1.6) D7(-3.6,1.6) D8(-3.6,2.4) D9(-3.6,3.2) E1(-2.8,-3.2) E2(-2.8,-2.4) E3(-2.8,-1.6) E7(-2.8,1.6) E8(-2.8,2.4) E9(-2.8,3.2) F1(-2,-3.2) F2(-2,-2.4) F3(-2,-1.6) F7(-2,1.6) F8(-2,2.4) F9(-2,3.2) G1(-1.2,-3.2) G2(-1.2,-2.4) G3(-1.2,-1.6) G7(-1.2,1.6) G8(-1.2,2.4) G9(-1.2,3.2) H1(-0.4,-3.2) H2(-0.4,-2.4) H3(-0.4,-1.6) H7(-0.4,1.6) H8(-0.4,2.4) H9(-0.4,3.2) J1(0.4,-3.2) J2(0.4,-2.4) J3(0.4,-1.6) J7(0.4,1.6) J8(0.4,2.4) J9(0.4,3.2) K1(1.2,-3.2) K2(1.2,-2.4) K3(1.2,-1.6) K7(1.2,1.6) K8(1.2,2.4) K9(1.2,3.2) L1(2,-3.2) L2(2,-2.4) L3(2,-1.6) L7(2,1.6) L8(2,2.4) L9(2,3.2) M1(2.8,-3.2) M2(2.8,-2.4) M3(2.8,-1.6) M7(2.8,1.6) M8(2.8,2.4) M9(2.8,3.2) N1(3.6,-3.2) N2(3.6,-2.4) N3(3.6,-1.6) N7(3.6,1.6) N8(3.6,2.4) N9(3.6,3.2) P1(4.4,-3.2) P2(4.4,-2.4) P3(4.4,-1.6) P7(4.4,1.6) P8(4.4,2.4) P9(4.4,3.2) R1(5.2,-3.2) R2(5.2,-2.4) R3(5.2,-1.6) R7(5.2,1.6) R8(5.2,2.4) R9(5.2,3.2) T1(6,-3.2) T2(6,-2.4) T3(6,-1.6) T7(6,1.6) T8(6,2.4) T9(6,3.2)
BGA_117P_39_551X394
  round 0.457 smd: A1(-6,-4) A2(-6,-3) A3(-6,-2) A4(-6,-1) A5(-6,0) A6(-6,1) A7(-6,2) A8(-6,3) A9(-6,4) B1(-5,-4) B2(-5,-3) B3(-5,-2) B4(-5,-1) B5(-5,0) B6(-5,1) B7(-5,2) B8(-5,3) B9(-5,4) C1(-4,-4) C2(-4,-3) C3(-4,-2) C4(-4,-1) C5(-4,0) C6(-4,1) C7(-4,2) C8(-4,3) C9(-4,4) D1(-3,-4) D2(-3,-3) D3(-3,-2) D4(-3,-1) D5(-3,0) D6(-3,1) D7(-3,2) D8(-3,3) D9(-3,4) E1(-2,-4) E2(-2,-3) E3(-2,-2) E4(-2,-1) E5(-2,0) E6(-2,1) E7(-2,2) E8(-2,3) E9(-2,4) F1(-1,-4) F2(-1,-3) F3(-1,-2) F4(-1,-1) F5(-1,0) F6(-1,1) F7(-1,2) F8(-1,3) F9(-1,4) G1(0,-4) G2(0,-3) G3(0,-2) G4(0,-1) G5(0,0) G6(0,1) G7(0,2) G8(0,3) G9(0,4) H1(1,-4) H2(1,-3) H3(1,-2) H4(1,-1) H5(1,0) H6(1,1) H7(1,2) H8(1,3) H9(1,4) J1(2,-4) J2(2,-3) J3(2,-2) J4(2,-1) J5(2,0) J6(2,1) J7(2,2) J8(2,3) J9(2,4) K1(3,-4) K2(3,-3) K3(3,-2) K4(3,-1) K5(3,0) K6(3,1) K7(3,2) K8(3,3) K9(3,4) L1(4,-4) L2(4,-3) L3(4,-2) L4(4,-1) L5(4,0) L6(4,1) L7(4,2) L8(4,3) L9(4,4) M1(5,-4) M2(5,-3) M3(5,-2) M4(5,-1) M5(5,0) M6(5,1) M7(5,2) M8(5,3) M9(5,4) N1(6,-4) N2(6,-3) N3(6,-2) N4(6,-1) N5(6,0) N6(6,1) N7(6,2) N8(6,3) N9(6,4)
BGA_1517P_39_1575X1575_H125
  round 0.533 smd: A2(-19,-18) A3(-19,-17) A37(-19,17) A38(-19,18) AU1(17,-19) AU39(17,19) AV1(18,-19) AV39(18,19) AW2(19,-18) AW3(19,-17) AW37(19,17) AW38(19,18) B1(-18,-19) B39(-18,19) C1(-17,-19) C39(-17,19)
  round 0.457 smd: A4(-19,-16) A5(-19,-15) A6(-19,-14) A7(-19,-13) A8(-19,-12) A9(-19,-11) A10(-19,-10) A11(-19,-9) A12(-19,-8) A13(-19,-7) A14(-19,-6) A15(-19,-5) A16(-19,-4) A17(-19,-3) A18(-19,-2) A19(-19,-1) A20(-19,0) A21(-19,1) A22(-19,2) A23(-19,3) A24(-19,4) A25(-19,5) A26(-19,6) A27(-19,7) A28(-19,8) A29(-19,9) A30(-19,10) A31(-19,11) A32(-19,12) A33(-19,13) A34(-19,14) A35(-19,15) A36(-19,16) AA1(1,-19) AA2(1,-18) AA3(1,-17) AA4(1,-16) AA5(1,-15) AA6(1,-14) AA7(1,-13) AA8(1,-12) AA9(1,-11) AA10(1,-10) AA11(1,-9) AA12(1,-8) AA13(1,-7) AA14(1,-6) AA15(1,-5) AA16(1,-4) AA17(1,-3) AA18(1,-2) AA19(1,-1) AA20(1,0) AA21(1,1) AA22(1,2) AA23(1,3) AA24(1,4) AA25(1,5) AA26(1,6) AA27(1,7) AA28(1,8) AA29(1,9) AA30(1,10) AA31(1,11) AA32(1,12) AA33(1,13) AA34(1,14) AA35(1,15) AA36(1,16) AA37(1,17) AA38(1,18) AA39(1,19) AB1(2,-19) AB2(2,-18) AB3(2,-17) AB4(2,-16) AB5(2,-15) AB6(2,-14) AB7(2,-13) AB8(2,-12) AB9(2,-11) AB10(2,-10) AB11(2,-9) AB12(2,-8) AB13(2,-7) AB14(2,-6) AB15(2,-5) AB16(2,-4) AB17(2,-3) AB18(2,-2) AB19(2,-1) AB20(2,0) AB21(2,1) AB22(2,2) AB23(2,3) AB24(2,4) AB25(2,5) AB26(2,6) AB27(2,7) AB28(2,8) AB29(2,9) AB30(2,10) AB31(2,11) AB32(2,12) AB33(2,13) AB34(2,14) AB35(2,15) AB36(2,16) AB37(2,17) AB38(2,18) AB39(2,19) AC1(3,-19) AC2(3,-18) AC3(3,-17) AC4(3,-16) AC5(3,-15) AC6(3,-14) AC7(3,-13) AC8(3,-12) AC9(3,-11) AC10(3,-10) AC11(3,-9) AC12(3,-8) AC13(3,-7) AC14(3,-6) AC15(3,-5) AC16(3,-4) AC17(3,-3) AC18(3,-2) AC19(3,-1) AC20(3,0) AC21(3,1) AC22(3,2) AC23(3,3) AC24(3,4) AC25(3,5) AC26(3,6) AC27(3,7) AC28(3,8) AC29(3,9) AC30(3,10) AC31(3,11) AC32(3,12) AC33(3,13) AC34(3,14) AC35(3,15) AC36(3,16) AC37(3,17) AC38(3,18) AC39(3,19) AD1(4,-19) AD2(4,-18) AD3(4,-17) AD4(4,-16) AD5(4,-15) AD6(4,-14) AD7(4,-13) AD8(4,-12) AD9(4,-11) AD10(4,-10) AD11(4,-9) AD12(4,-8) AD13(4,-7) AD14(4,-6) AD15(4,-5) AD16(4,-4) AD17(4,-3) AD18(4,-2) AD19(4,-1) AD20(4,0) AD21(4,1) AD22(4,2) AD23(4,3) AD24(4,4) AD25(4,5) AD26(4,6) AD27(4,7) AD28(4,8) AD29(4,9) AD30(4,10) AD31(4,11) AD32(4,12) AD33(4,13) AD34(4,14) AD35(4,15) AD36(4,16) AD37(4,17) AD38(4,18) AD39(4,19) AE1(5,-19) AE2(5,-18) AE3(5,-17) AE4(5,-16) AE5(5,-15) AE6(5,-14) AE7(5,-13) AE8(5,-12) AE9(5,-11) AE10(5,-10) AE11(5,-9) AE12(5,-8) AE13(5,-7) AE14(5,-6) AE15(5,-5) AE16(5,-4) AE17(5,-3) AE18(5,-2) AE19(5,-1) AE20(5,0) AE21(5,1) AE22(5,2) AE23(5,3) AE24(5,4) AE25(5,5) AE26(5,6) AE27(5,7) AE28(5,8) AE29(5,9) AE30(5,10) AE31(5,11) AE32(5,12) AE33(5,13) AE34(5,14) AE35(5,15) AE36(5,16) AE37(5,17) AE38(5,18) AE39(5,19) AF1(6,-19) AF2(6,-18) AF3(6,-17) AF4(6,-16) AF5(6,-15) AF6(6,-14) AF7(6,-13) AF8(6,-12) AF9(6,-11) AF10(6,-10) AF11(6,-9) AF12(6,-8) AF13(6,-7) AF14(6,-6) AF15(6,-5) AF16(6,-4) AF17(6,-3) AF18(6,-2) AF19(6,-1) AF20(6,0) AF21(6,1) AF22(6,2) AF23(6,3) AF24(6,4) AF25(6,5) AF26(6,6) AF27(6,7) AF28(6,8) AF29(6,9) AF30(6,10) AF31(6,11) AF32(6,12) AF33(6,13) AF34(6,14) AF35(6,15) AF36(6,16) AF37(6,17) AF38(6,18) AF39(6,19) AG1(7,-19) AG2(7,-18) AG3(7,-17) AG4(7,-16) AG5(7,-15) AG6(7,-14) AG7(7,-13) AG8(7,-12) AG9(7,-11) AG10(7,-10) AG11(7,-9) AG12(7,-8) AG13(7,-7) AG14(7,-6) AG15(7,-5) AG16(7,-4) AG17(7,-3) AG18(7,-2) AG19(7,-1) AG20(7,0) AG21(7,1) AG22(7,2) AG23(7,3) AG24(7,4) AG25(7,5) AG26(7,6) AG27(7,7) AG28(7,8) AG29(7,9) AG30(7,10) AG31(7,11) AG32(7,12) AG33(7,13) AG34(7,14) AG35(7,15) AG36(7,16) AG37(7,17) AG38(7,18) AG39(7,19) AH1(8,-19) AH2(8,-18) AH3(8,-17) AH4(8,-16) AH5(8,-15) AH6(8,-14) AH7(8,-13) AH8(8,-12) AH9(8,-11) AH10(8,-10) AH11(8,-9) AH12(8,-8) AH13(8,-7) AH14(8,-6) AH15(8,-5) AH16(8,-4) AH17(8,-3) AH18(8,-2) AH19(8,-1) AH20(8,0) AH21(8,1) AH22(8,2) AH23(8,3) AH24(8,4) AH25(8,5) AH26(8,6) AH27(8,7) AH28(8,8) AH29(8,9) AH30(8,10) AH31(8,11) AH32(8,12) AH33(8,13) AH34(8,14) AH35(8,15) AH36(8,16) AH37(8,17) AH38(8,18) AH39(8,19) AJ1(9,-19) AJ2(9,-18) AJ3(9,-17) AJ4(9,-16) AJ5(9,-15) AJ6(9,-14) AJ7(9,-13) AJ8(9,-12) AJ9(9,-11) AJ10(9,-10) AJ11(9,-9) AJ12(9,-8) AJ13(9,-7) AJ14(9,-6) AJ15(9,-5) AJ16(9,-4) AJ17(9,-3) AJ18(9,-2) AJ19(9,-1) AJ20(9,0) AJ21(9,1) AJ22(9,2) AJ23(9,3) AJ24(9,4) AJ25(9,5) AJ26(9,6) AJ27(9,7) AJ28(9,8) AJ29(9,9) AJ30(9,10) AJ31(9,11) AJ32(9,12) AJ33(9,13) AJ34(9,14) AJ35(9,15) AJ36(9,16) AJ37(9,17) AJ38(9,18) AJ39(9,19) AK1(10,-19) AK2(10,-18) AK3(10,-17) AK4(10,-16) AK5(10,-15) AK6(10,-14) AK7(10,-13) AK8(10,-12) AK9(10,-11) AK10(10,-10) AK11(10,-9) AK12(10,-8) AK13(10,-7) AK14(10,-6) AK15(10,-5) AK16(10,-4) AK17(10,-3) AK18(10,-2) AK19(10,-1) AK20(10,0) AK21(10,1) AK22(10,2) AK23(10,3) AK24(10,4) AK25(10,5) AK26(10,6) AK27(10,7) AK28(10,8) AK29(10,9) AK30(10,10) AK31(10,11) AK32(10,12) AK33(10,13) AK34(10,14) AK35(10,15) AK36(10,16) AK37(10,17) AK38(10,18) AK39(10,19) AL1(11,-19) AL2(11,-18) AL3(11,-17) AL4(11,-16) AL5(11,-15) AL6(11,-14) AL7(11,-13) AL8(11,-12) AL9(11,-11) AL10(11,-10) AL11(11,-9) AL12(11,-8) AL13(11,-7) AL14(11,-6) AL15(11,-5) AL16(11,-4) AL17(11,-3) AL18(11,-2) AL19(11,-1) AL20(11,0) AL21(11,1) AL22(11,2) AL23(11,3) AL24(11,4) AL25(11,5) AL26(11,6) AL27(11,7) AL28(11,8) AL29(11,9) AL30(11,10) AL31(11,11) AL32(11,12) AL33(11,13) AL34(11,14) AL35(11,15) AL36(11,16) AL37(11,17) AL38(11,18) AL39(11,19) AM1(12,-19) AM2(12,-18) AM3(12,-17) AM4(12,-16) AM5(12,-15) AM6(12,-14) AM7(12,-13) AM8(12,-12) AM9(12,-11) AM10(12,-10) AM11(12,-9) AM12(12,-8) AM13(12,-7) AM14(12,-6) AM15(12,-5) AM16(12,-4) AM17(12,-3) AM18(12,-2) AM19(12,-1) AM20(12,0) AM21(12,1) AM22(12,2) AM23(12,3) AM24(12,4) AM25(12,5) AM26(12,6) AM27(12,7) AM28(12,8) AM29(12,9) AM30(12,10) AM31(12,11) AM32(12,12) AM33(12,13) AM34(12,14) AM35(12,15) AM36(12,16) AM37(12,17) AM38(12,18) AM39(12,19) AN1(13,-19) AN2(13,-18) AN3(13,-17) AN4(13,-16) AN5(13,-15) AN6(13,-14) AN7(13,-13) AN8(13,-12) AN9(13,-11) AN10(13,-10) AN11(13,-9) AN12(13,-8) AN13(13,-7) AN14(13,-6) AN15(13,-5) AN16(13,-4) AN17(13,-3) AN18(13,-2) AN19(13,-1) AN20(13,0) AN21(13,1) AN22(13,2) AN23(13,3) AN24(13,4) AN25(13,5) AN26(13,6) AN27(13,7) AN28(13,8) AN29(13,9) AN30(13,10) AN31(13,11) AN32(13,12) AN33(13,13) AN34(13,14) AN35(13,15) AN36(13,16) AN37(13,17) AN38(13,18) AN39(13,19) AP1(14,-19) AP2(14,-18) AP3(14,-17) AP4(14,-16) AP5(14,-15) AP6(14,-14) AP7(14,-13) AP8(14,-12) AP9(14,-11) AP10(14,-10) AP11(14,-9) AP12(14,-8) AP13(14,-7) AP14(14,-6) AP15(14,-5) AP16(14,-4) AP17(14,-3) AP18(14,-2) AP19(14,-1) AP20(14,0) AP21(14,1) AP22(14,2) AP23(14,3) AP24(14,4) AP25(14,5) AP26(14,6) AP27(14,7) AP28(14,8) AP29(14,9) AP30(14,10) AP31(14,11) AP32(14,12) AP33(14,13) AP34(14,14) AP35(14,15) AP36(14,16) AP37(14,17) AP38(14,18) AP39(14,19) AR1(15,-19) AR2(15,-18) AR3(15,-17) AR4(15,-16) AR5(15,-15) AR6(15,-14) AR7(15,-13) AR8(15,-12) AR9(15,-11) AR10(15,-10) AR11(15,-9) AR12(15,-8) AR13(15,-7) AR14(15,-6) AR15(15,-5) AR16(15,-4) AR17(15,-3) AR18(15,-2) AR19(15,-1) AR20(15,0) AR21(15,1) AR22(15,2) AR23(15,3) AR24(15,4) AR25(15,5) AR26(15,6) AR27(15,7) AR28(15,8) AR29(15,9) AR30(15,10) AR31(15,11) AR32(15,12) AR33(15,13) AR34(15,14) AR35(15,15) AR36(15,16) AR37(15,17) AR38(15,18) AR39(15,19) AT1(16,-19) AT2(16,-18) AT3(16,-17) AT4(16,-16) AT5(16,-15) AT6(16,-14) AT7(16,-13) AT8(16,-12) AT9(16,-11) AT10(16,-10) AT11(16,-9) AT12(16,-8) AT13(16,-7) AT14(16,-6) AT15(16,-5) AT16(16,-4) AT17(16,-3) AT18(16,-2) AT19(16,-1) AT20(16,0) AT21(16,1) AT22(16,2) AT23(16,3) AT24(16,4) AT25(16,5) AT26(16,6) AT27(16,7) AT28(16,8) AT29(16,9) AT30(16,10) AT31(16,11) AT32(16,12) AT33(16,13) AT34(16,14) AT35(16,15) AT36(16,16) AT37(16,17) AT38(16,18) AT39(16,19) AU2(17,-18) AU3(17,-17) AU4(17,-16) AU5(17,-15) AU6(17,-14) AU7(17,-13) AU8(17,-12) AU9(17,-11) AU10(17,-10) AU11(17,-9) AU12(17,-8) AU13(17,-7) AU14(17,-6) AU15(17,-5) AU16(17,-4) AU17(17,-3) AU18(17,-2) AU19(17,-1) AU20(17,0) AU21(17,1) AU22(17,2) AU23(17,3) AU24(17,4) AU25(17,5) AU26(17,6) AU27(17,7) AU28(17,8) AU29(17,9) AU30(17,10) AU31(17,11) AU32(17,12) AU33(17,13) AU34(17,14) AU35(17,15) AU36(17,16) AU37(17,17) AU38(17,18) AV2(18,-18) AV3(18,-17) AV4(18,-16) AV5(18,-15) AV6(18,-14) AV7(18,-13) AV8(18,-12) AV9(18,-11) AV10(18,-10) AV11(18,-9) AV12(18,-8) AV13(18,-7) AV14(18,-6) AV15(18,-5) AV16(18,-4) AV17(18,-3) AV18(18,-2) AV19(18,-1) AV20(18,0) AV21(18,1) AV22(18,2) AV23(18,3) AV24(18,4) AV25(18,5) AV26(18,6) AV27(18,7) AV28(18,8) AV29(18,9) AV30(18,10) AV31(18,11) AV32(18,12) AV33(18,13) AV34(18,14) AV35(18,15) AV36(18,16) AV37(18,17) AV38(18,18) AW4(19,-16) AW5(19,-15) AW6(19,-14) AW7(19,-13) AW8(19,-12) AW9(19,-11) AW10(19,-10) AW11(19,-9) AW12(19,-8) AW13(19,-7) AW14(19,-6) AW15(19,-5) AW16(19,-4) AW17(19,-3) AW18(19,-2) AW19(19,-1) AW20(19,0) AW21(19,1) AW22(19,2) AW23(19,3) AW24(19,4) AW25(19,5) AW26(19,6) AW27(19,7) AW28(19,8) AW29(19,9) AW30(19,10) AW31(19,11) AW32(19,12) AW33(19,13) AW34(19,14) AW35(19,15) AW36(19,16) B2(-18,-18) B3(-18,-17) B4(-18,-16) B5(-18,-15) B6(-18,-14) B7(-18,-13) B8(-18,-12) B9(-18,-11) B10(-18,-10) B11(-18,-9) B12(-18,-8) B13(-18,-7) B14(-18,-6) B15(-18,-5) B16(-18,-4) B17(-18,-3) B18(-18,-2) B19(-18,-1) B20(-18,0) B21(-18,1) B22(-18,2) B23(-18,3) B24(-18,4) B25(-18,5) B26(-18,6) B27(-18,7) B28(-18,8) B29(-18,9) B30(-18,10) B31(-18,11) B32(-18,12) B33(-18,13) B34(-18,14) B35(-18,15) B36(-18,16) B37(-18,17) B38(-18,18) C2(-17,-18) C3(-17,-17) C4(-17,-16) C5(-17,-15) C6(-17,-14) C7(-17,-13) C8(-17,-12) C9(-17,-11) C10(-17,-10) C11(-17,-9) C12(-17,-8) C13(-17,-7) C14(-17,-6) C15(-17,-5) C16(-17,-4) C17(-17,-3) C18(-17,-2) C19(-17,-1) C20(-17,0) C21(-17,1) C22(-17,2) C23(-17,3) C24(-17,4) C25(-17,5) C26(-17,6) C27(-17,7) C28(-17,8) C29(-17,9) C30(-17,10) C31(-17,11) C32(-17,12) C33(-17,13) C34(-17,14) C35(-17,15) C36(-17,16) C37(-17,17) C38(-17,18) D1(-16,-19) D2(-16,-18) D3(-16,-17) D4(-16,-16) D5(-16,-15) D6(-16,-14) D7(-16,-13) D8(-16,-12) D9(-16,-11) D10(-16,-10) D11(-16,-9) D12(-16,-8) D13(-16,-7) D14(-16,-6) D15(-16,-5) D16(-16,-4) D17(-16,-3) D18(-16,-2) D19(-16,-1) D20(-16,0) D21(-16,1) D22(-16,2) D23(-16,3) D24(-16,4) D25(-16,5) D26(-16,6) D27(-16,7) D28(-16,8) D29(-16,9) D30(-16,10) D31(-16,11) D32(-16,12) D33(-16,13) D34(-16,14) D35(-16,15) D36(-16,16) D37(-16,17) D38(-16,18) D39(-16,19) E1(-15,-19) E2(-15,-18) E3(-15,-17) E4(-15,-16) E5(-15,-15) E6(-15,-14) E7(-15,-13) E8(-15,-12) E9(-15,-11) E10(-15,-10) E11(-15,-9) E12(-15,-8) E13(-15,-7) E14(-15,-6) E15(-15,-5) E16(-15,-4) E17(-15,-3) E18(-15,-2) E19(-15,-1) E20(-15,0) E21(-15,1) E22(-15,2) E23(-15,3) E24(-15,4) E25(-15,5) E26(-15,6) E27(-15,7) E28(-15,8) E29(-15,9) E30(-15,10) E31(-15,11) E32(-15,12) E33(-15,13) E34(-15,14) E35(-15,15) E36(-15,16) E37(-15,17) E38(-15,18) E39(-15,19) F1(-14,-19) F2(-14,-18) F3(-14,-17) F4(-14,-16) F5(-14,-15) F6(-14,-14) F7(-14,-13) F8(-14,-12) F9(-14,-11) F10(-14,-10) F11(-14,-9) F12(-14,-8) F13(-14,-7) F14(-14,-6) F15(-14,-5) F16(-14,-4) F17(-14,-3) F18(-14,-2) F19(-14,-1) F20(-14,0) F21(-14,1) F22(-14,2) F23(-14,3) F24(-14,4) F25(-14,5) F26(-14,6) F27(-14,7) F28(-14,8) F29(-14,9) F30(-14,10) F31(-14,11) F32(-14,12) F33(-14,13) F34(-14,14) F35(-14,15) F36(-14,16) F37(-14,17) F38(-14,18) F39(-14,19) G1(-13,-19) G2(-13,-18) G3(-13,-17) G4(-13,-16) G5(-13,-15) G6(-13,-14) G7(-13,-13) G8(-13,-12) G9(-13,-11) G10(-13,-10) G11(-13,-9) G12(-13,-8) G13(-13,-7) G14(-13,-6) G15(-13,-5) G16(-13,-4) G17(-13,-3) G18(-13,-2) G19(-13,-1) G20(-13,0) G21(-13,1) G22(-13,2) G23(-13,3) G24(-13,4) G25(-13,5) G26(-13,6) G27(-13,7) G28(-13,8) G29(-13,9) G30(-13,10) G31(-13,11) G32(-13,12) G33(-13,13) G34(-13,14) G35(-13,15) G36(-13,16) G37(-13,17) G38(-13,18) G39(-13,19) H1(-12,-19) H2(-12,-18) H3(-12,-17) H4(-12,-16) H5(-12,-15) H6(-12,-14) H7(-12,-13) H8(-12,-12) H9(-12,-11) H10(-12,-10) H11(-12,-9) H12(-12,-8) H13(-12,-7) H14(-12,-6) H15(-12,-5) H16(-12,-4) H17(-12,-3) H18(-12,-2) H19(-12,-1) H20(-12,0) H21(-12,1) H22(-12,2) H23(-12,3) H24(-12,4) H25(-12,5) H26(-12,6) H27(-12,7) H28(-12,8) H29(-12,9) H30(-12,10) H31(-12,11) H32(-12,12) H33(-12,13) H34(-12,14) H35(-12,15) H36(-12,16) H37(-12,17) H38(-12,18) H39(-12,19) J1(-11,-19) J2(-11,-18) J3(-11,-17) J4(-11,-16) J5(-11,-15) J6(-11,-14) J7(-11,-13) J8(-11,-12) J9(-11,-11) J10(-11,-10) J11(-11,-9) J12(-11,-8) J13(-11,-7) J14(-11,-6) J15(-11,-5) J16(-11,-4) J17(-11,-3) J18(-11,-2) J19(-11,-1) J20(-11,0) J21(-11,1) J22(-11,2) J23(-11,3) J24(-11,4) J25(-11,5) J26(-11,6) J27(-11,7) J28(-11,8) J29(-11,9) J30(-11,10) J31(-11,11) J32(-11,12) J33(-11,13) J34(-11,14) J35(-11,15) J36(-11,16) J37(-11,17) J38(-11,18) J39(-11,19) K1(-10,-19) K2(-10,-18) K3(-10,-17) K4(-10,-16) K5(-10,-15) K6(-10,-14) K7(-10,-13) K8(-10,-12) K9(-10,-11) K10(-10,-10) K11(-10,-9) K12(-10,-8) K13(-10,-7) K14(-10,-6) K15(-10,-5) K16(-10,-4) K17(-10,-3) K18(-10,-2) K19(-10,-1) K20(-10,0) K21(-10,1) K22(-10,2) K23(-10,3) K24(-10,4) K25(-10,5) K26(-10,6) K27(-10,7) K28(-10,8) K29(-10,9) K30(-10,10) K31(-10,11) K32(-10,12) K33(-10,13) K34(-10,14) K35(-10,15) K36(-10,16) K37(-10,17) K38(-10,18) K39(-10,19) L1(-9,-19) L2(-9,-18) L3(-9,-17) L4(-9,-16) L5(-9,-15) L6(-9,-14) L7(-9,-13) L8(-9,-12) L9(-9,-11) L10(-9,-10) L11(-9,-9) L12(-9,-8) L13(-9,-7) L14(-9,-6) L15(-9,-5) L16(-9,-4) L17(-9,-3) L18(-9,-2) L19(-9,-1) L20(-9,0) L21(-9,1) L22(-9,2) L23(-9,3) L24(-9,4) L25(-9,5) L26(-9,6) L27(-9,7) L28(-9,8) L29(-9,9) L30(-9,10) L31(-9,11) L32(-9,12) L33(-9,13) L34(-9,14) L35(-9,15) L36(-9,16) L37(-9,17) L38(-9,18) L39(-9,19) M1(-8,-19) M2(-8,-18) M3(-8,-17) M4(-8,-16) M5(-8,-15) M6(-8,-14) M7(-8,-13) M8(-8,-12) M9(-8,-11) M10(-8,-10) M11(-8,-9) M12(-8,-8) M13(-8,-7) M14(-8,-6) M15(-8,-5) M16(-8,-4) M17(-8,-3) M18(-8,-2) M19(-8,-1) M20(-8,0) M21(-8,1) M22(-8,2) M23(-8,3) M24(-8,4) M25(-8,5) M26(-8,6) M27(-8,7) M28(-8,8) M29(-8,9) M30(-8,10) M31(-8,11) M32(-8,12) M33(-8,13) M34(-8,14) M35(-8,15) M36(-8,16) M37(-8,17) M38(-8,18) M39(-8,19) N1(-7,-19) N2(-7,-18) N3(-7,-17) N4(-7,-16) N5(-7,-15) N6(-7,-14) N7(-7,-13) N8(-7,-12) N9(-7,-11) N10(-7,-10) N11(-7,-9) N12(-7,-8) N13(-7,-7) N14(-7,-6) N15(-7,-5) N16(-7,-4) N17(-7,-3) N18(-7,-2) N19(-7,-1) N20(-7,0) N21(-7,1) N22(-7,2) N23(-7,3) N24(-7,4) N25(-7,5) N26(-7,6) N27(-7,7) N28(-7,8) N29(-7,9) N30(-7,10) N31(-7,11) N32(-7,12) N33(-7,13) N34(-7,14) N35(-7,15) N36(-7,16) N37(-7,17) N38(-7,18) N39(-7,19) P1(-6,-19) P2(-6,-18) P3(-6,-17) P4(-6,-16) P5(-6,-15) P6(-6,-14) P7(-6,-13) P8(-6,-12) P9(-6,-11) P10(-6,-10) P11(-6,-9) P12(-6,-8) P13(-6,-7) P14(-6,-6) P15(-6,-5) P16(-6,-4) P17(-6,-3) P18(-6,-2) P19(-6,-1) P20(-6,0) P21(-6,1) P22(-6,2) P23(-6,3) P24(-6,4) P25(-6,5) P26(-6,6) P27(-6,7) P28(-6,8) P29(-6,9) P30(-6,10) P31(-6,11) P32(-6,12) P33(-6,13) P34(-6,14) P35(-6,15) P36(-6,16) P37(-6,17) P38(-6,18) P39(-6,19) R1(-5,-19) R2(-5,-18) R3(-5,-17) R4(-5,-16) R5(-5,-15) R6(-5,-14) R7(-5,-13) R8(-5,-12) R9(-5,-11) R10(-5,-10) R11(-5,-9) R12(-5,-8) R13(-5,-7) R14(-5,-6) R15(-5,-5) R16(-5,-4) R17(-5,-3) R18(-5,-2) R19(-5,-1) R20(-5,0) R21(-5,1) R22(-5,2) R23(-5,3) R24(-5,4) R25(-5,5) R26(-5,6) R27(-5,7) R28(-5,8) R29(-5,9) R30(-5,10) R31(-5,11) R32(-5,12) R33(-5,13) R34(-5,14) R35(-5,15) R36(-5,16) R37(-5,17) R38(-5,18) R39(-5,19) T1(-4,-19) T2(-4,-18) T3(-4,-17) T4(-4,-16) T5(-4,-15) T6(-4,-14) T7(-4,-13) T8(-4,-12) T9(-4,-11) T10(-4,-10) T11(-4,-9) T12(-4,-8) T13(-4,-7) T14(-4,-6) T15(-4,-5) T16(-4,-4) T17(-4,-3) T18(-4,-2) T19(-4,-1) T20(-4,0) T21(-4,1) T22(-4,2) T23(-4,3) T24(-4,4) T25(-4,5) T26(-4,6) T27(-4,7) T28(-4,8) T29(-4,9) T30(-4,10) T31(-4,11) T32(-4,12) T33(-4,13) T34(-4,14) T35(-4,15) T36(-4,16) T37(-4,17) T38(-4,18) T39(-4,19) U1(-3,-19) U2(-3,-18) U3(-3,-17) U4(-3,-16) U5(-3,-15) U6(-3,-14) U7(-3,-13) U8(-3,-12) U9(-3,-11) U10(-3,-10) U11(-3,-9) U12(-3,-8) U13(-3,-7) U14(-3,-6) U15(-3,-5) U16(-3,-4) U17(-3,-3) U18(-3,-2) U19(-3,-1) U20(-3,0) U21(-3,1) U22(-3,2) U23(-3,3) U24(-3,4) U25(-3,5) U26(-3,6) U27(-3,7) U28(-3,8) U29(-3,9) U30(-3,10) U31(-3,11) U32(-3,12) U33(-3,13) U34(-3,14) U35(-3,15) U36(-3,16) U37(-3,17) U38(-3,18) U39(-3,19) V1(-2,-19) V2(-2,-18) V3(-2,-17) V4(-2,-16) V5(-2,-15) V6(-2,-14) V7(-2,-13) V8(-2,-12) V9(-2,-11) V10(-2,-10) V11(-2,-9) V12(-2,-8) V13(-2,-7) V14(-2,-6) V15(-2,-5) V16(-2,-4) V17(-2,-3) V18(-2,-2) V19(-2,-1) V20(-2,0) V21(-2,1) V22(-2,2) V23(-2,3) V24(-2,4) V25(-2,5) V26(-2,6) V27(-2,7) V28(-2,8) V29(-2,9) V30(-2,10) V31(-2,11) V32(-2,12) V33(-2,13) V34(-2,14) V35(-2,15) V36(-2,16) V37(-2,17) V38(-2,18) V39(-2,19) W1(-1,-19) W2(-1,-18) W3(-1,-17) W4(-1,-16) W5(-1,-15) W6(-1,-14) W7(-1,-13) W8(-1,-12) W9(-1,-11) W10(-1,-10) W11(-1,-9) W12(-1,-8) W13(-1,-7) W14(-1,-6) W15(-1,-5) W16(-1,-4) W17(-1,-3) W18(-1,-2) W19(-1,-1) W20(-1,0) W21(-1,1) W22(-1,2) W23(-1,3) W24(-1,4) W25(-1,5) W26(-1,6) W27(-1,7) W28(-1,8) W29(-1,9) W30(-1,10) W31(-1,11) W32(-1,12) W33(-1,13) W34(-1,14) W35(-1,15) W36(-1,16) W37(-1,17) W38(-1,18) W39(-1,19) Y1(0,-19) Y2(0,-18) Y3(0,-17) Y4(0,-16) Y5(0,-15) Y6(0,-14) Y7(0,-13) Y8(0,-12) Y9(0,-11) Y10(0,-10) Y11(0,-9) Y12(0,-8) Y13(0,-7) Y14(0,-6) Y15(0,-5) Y16(0,-4) Y17(0,-3) Y18(0,-2) Y19(0,-1) Y20(0,0) Y21(0,1) Y22(0,2) Y23(0,3) Y24(0,4) Y25(0,5) Y26(0,6) Y27(0,7) Y28(0,8) Y29(0,9) Y30(0,10) Y31(0,11) Y32(0,12) Y33(0,13) Y34(0,14) Y35(0,15) Y36(0,16) Y37(0,17) Y38(0,18) Y39(0,19)
C0402
  oval 0.711x0.381 smd: 1(0,0.45) 2(0,-0.45)
C0603
  oval 1.016x0.813 smd: 1(0,0.826) 2(0,-0.826)
C0805
  oval 1.778x0.889 smd: 1(0,-1.016) 2(0,1.016)
C1206-1
  custom 0.349x0.349 smd: 1(-1.15,0) 2(1.15,0)
C_2P_114_138X118
  rect 1.194x2.311 smd: 1(-1.448,0) 2(1.448,0)
C_2P_244_287X177
  rect 2.489x1.702 smd: 1(0,3.098) 2(0,-3.098)
C_2P_244_287X177_H110
  rect 2.388x2.235 smd: 1(0,3.373) 2(0,-3.373)
C_2P_244_295X177
  rect 2.388x2.565 smd: 1(0,3.332) 2(0,-3.332)
CHOKE_2P_238_287X260
  rect 2.845x3.302 smd: 1(-3.023,0) 2(3.023,0)
COAXIAL_4P_MM8030-2610
  rect 0.508x0.406 smd: 1(0,-0.95) 2(0,0.95)
  rect 0.711x1.092 smd: H1(-0.8,0) H2(0.8,0)
DDR3_204P_DDRSK-20401-TP65
  round 1.092 hole 1.092 unplated: (-33.4,0)
  round 1.6 hole 1.6 unplated: (33.4,0)
  oval 0.356x2.007 smd: 1(31.65,4.1) 2(31.35,-4.1) 3(31.05,4.1) 4(30.75,-4.1) 5(30.45,4.1) 6(30.15,-4.1) 7(29.85,4.1) 8(29.55,-4.1) 9(29.25,4.1) 10(28.95,-4.1) 11(28.65,4.1) 12(28.35,-4.1) 13(28.05,4.1) 14(27.75,-4.1) 15(27.45,4.1) 16(27.15,-4.1) 17(26.85,4.1) 18(26.55,-4.1) 19(26.25,4.1) 20(25.95,-4.1) 21(25.65,4.1) 22(25.35,-4.1) 23(25.05,4.1) 24(24.75,-4.1) 25(24.45,4.1) 26(24.15,-4.1) 27(23.85,4.1) 28(23.55,-4.1) 29(23.25,4.1) 30(22.95,-4.1) 31(22.65,4.1) 32(22.35,-4.1) 33(22.05,4.1) 34(21.75,-4.1) 35(21.45,4.1) 36(21.15,-4.1) 37(20.85,4.1) 38(20.55,-4.1) 39(20.25,4.1) 40(19.95,-4.1) 41(19.65,4.1) 42(19.35,-4.1) 43(19.05,4.1) 44(18.75,-4.1) 45(18.45,4.1) 46(18.15,-4.1) 47(17.85,4.1) 48(17.55,-4.1) 49(17.25,4.1) 50(16.95,-4.1) 51(16.65,4.1) 52(16.35,-4.1) 53(16.05,4.1) 54(15.75,-4.1) 55(15.45,4.1) 56(15.15,-4.1) 57(14.85,4.1) 58(14.55,-4.1) 59(14.25,4.1) 60(13.95,-4.1) 61(13.65,4.1) 62(13.35,-4.1) 63(13.05,4.1) 64(12.75,-4.1) 65(12.45,4.1) 66(12.15,-4.1) 67(11.85,4.1) 68(11.55,-4.1) 69(11.25,4.1) 70(10.95,-4.1) 71(10.65,4.1) 72(10.35,-4.1) 73(7.65,4.1) 74(7.35,-4.1) 75(7.05,4.1) 76(6.75,-4.1) 77(6.45,4.1) 78(6.15,-4.1) 79(5.85,4.1) 80(5.55,-4.1) 81(5.25,4.1) 82(4.95,-4.1) 83(4.65,4.1) 84(4.35,-4.1) 85(4.05,4.1) 86(3.75,-4.1) 87(3.45,4.1) 88(3.15,-4.1) 89(2.85,4.1) 90(2.55,-4.1) 91(2.25,4.1) 92(1.95,-4.1) 93(1.65,4.1) 94(1.35,-4.1) 95(1.05,4.1) 96(0.75,-4.1) 97(0.45,4.1) 98(0.15,-4.1) 99(-0.15,4.1) 100(-0.45,-4.1) 101(-0.75,4.1) 102(-1.05,-4.1) 103(-1.35,4.1) 104(-1.65,-4.1) 105(-1.95,4.1) 106(-2.25,-4.1) 107(-2.55,4.1) 108(-2.85,-4.1) 109(-3.15,4.1) 110(-3.45,-4.1) 111(-3.75,4.1) 112(-4.05,-4.1) 113(-4.35,4.1) 114(-4.65,-4.1) 115(-4.95,4.1) 116(-5.25,-4.1) 117(-5.55,4.1) 118(-5.85,-4.1) 119(-6.15,4.1) 120(-6.45,-4.1) 121(-6.75,4.1) 122(-7.05,-4.1) 123(-7.35,4.1) 124(-7.65,-4.1) 125(-7.95,4.1) 126(-8.25,-4.1) 127(-8.55,4.1) 128(-8.85,-4.1) 129(-9.15,4.1) 130(-9.45,-4.1) 131(-9.75,4.1) 132(-10.05,-4.1) 133(-10.35,4.1) 134(-10.65,-4.1) 135(-10.95,4.1) 136(-11.25,-4.1) 137(-11.55,4.1) 138(-11.85,-4.1) 139(-12.15,4.1) 140(-12.45,-4.1) 141(-12.75,4.1) 142(-13.05,-4.1) 143(-13.35,4.1) 144(-13.65,-4.1) 145(-13.95,4.1) 146(-14.25,-4.1) 147(-14.55,4.1) 148(-14.85,-4.1) 149(-15.15,4.1) 150(-15.45,-4.1) 151(-15.75,4.1) 152(-16.05,-4.1) 153(-16.35,4.1) 154(-16.65,-4.1) 155(-16.95,4.1) 156(-17.25,-4.1) 157(-17.55,4.1) 158(-17.85,-4.1) 159(-18.15,4.1) 160(-18.45,-4.1) 161(-18.75,4.1) 162(-19.05,-4.1) 163(-19.35,4.1) 164(-19.65,-4.1) 165(-19.95,4.1) 166(-20.25,-4.1) 167(-20.55,4.1) 168(-20.85,-4.1) 169(-21.15,4.1) 170(-21.45,-4.1) 171(-21.75,4.1) 172(-22.05,-4.1) 173(-22.35,4.1) 174(-22.65,-4.1) 175(-22.95,4.1) 176(-23.25,-4.1) 177(-23.55,4.1) 178(-23.85,-4.1) 179(-24.15,4.1) 180(-24.45,-4.1) 181(-24.75,4.1) 182(-25.05,-4.1) 183(-25.35,4.1) 184(-25.65,-4.1) 185(-25.95,4.1) 186(-26.25,-4.1) 187(-26.55,4.1) 188(-26.85,-4.1) 189(-27.15,4.1) 190(-27.45,-4.1) 191(-27.75,4.1) 192(-28.05,-4.1) 193(-28.35,4.1) 194(-28.65,-4.1) 195(-28.95,4.1) 196(-29.25,-4.1) 197(-29.55,4.1) 198(-29.85,-4.1) 199(-30.15,4.1) 200(-30.45,-4.1) 201(-30.75,4.1) 202(-31.05,-4.1) 203(-31.35,4.1) 204(-31.65,-4.1)
  rect 3.505x4.597 smd: H3(-32.8,-12) H4(32.8,-12)
DIODE_2P_36_40X27
  rect 0.711x0.584 smd: 1(-0.455,0) 2(0.455,0)
DIODE_2P_78_79X55
  oval 0.787x1.397 smd: 1(-0.994,0) 2(0.994,0)
DIODE_2P_146_106X61_ANODE2
  oval 0.686x1.016 smd: 1(0,-1.852) 2(0,1.852)
FIDUCIAL
  round 1.016 smd: 1(0,0)
GF-AMC-B
  rect 0.483x0.965 smd: (-30.749,1.066) (-29.999,1.066) (-29.249,1.066) (-28.499,1.067) (-28.499,1.066) (-27.749,1.067) (-27.748,1.066) (-26.249,1.066) (-19.5,1.067) (-12.748,1.069) (-1.5,1.069) (9.749,1.068) (21.001,1.068)
  rect 0.483x2.007 smd: (-30.001,0.548) (30,0.546)
  rect 0.483x1.702 smd: (-26.249,0.699) (-25.499,0.699) (-24,0.699) (-23.999,0.699) (-23.249,0.699) (-23.248,0.699) (-21.748,0.699) (-21.748,0.699) (-21,0.699) (-21,0.699) (-19.501,0.699) (-18.749,0.699) (-17.248,0.699) (-17.248,0.699) (-16.5,0.699) (-16.5,0.699) (-15,0.699) (-15,0.699) (-14.248,0.699) (-14.248,0.699) (-12.748,0.698) (-12,0.698) (-10.5,0.699) (-10.5,0.699) (-9.752,0.699) (-9.752,0.699) (-8.248,0.699) (-8.248,0.699) (-7.5,0.699) (-7.5,0.699) (-6,0.699) (-6,0.699) (-5.252,0.699) (-5.252,0.699) (-3.752,0.699) (-3.752,0.699) (-3,0.699) (-3,0.699) (-1.5,0.699) (-0.752,0.699) (0.748,0.699) (0.749,0.699) (1.5,0.699) (1.501,0.699) (3.001,0.699) (3.001,0.699) (3.749,0.699) (3.749,0.699) (5.249,0.699) (5.249,0.699) (6.001,0.699) (6.001,0.699) (7.501,0.699) (7.501,0.699) (8.249,0.699) (8.249,0.699) (9.749,0.698) (10.501,0.698) (12.001,0.699) (12.001,0.699) (12.749,0.699) (12.749,0.699) (14.249,0.699) (14.249,0.699) (15.001,0.699) (15.001,0.699) (16.501,0.699) (16.501,0.699) (17.249,0.699) (17.249,0.699) (18.749,0.699) (18.749,0.699) (19.501,0.699) (19.501,0.699) (21.001,0.699) (21.75,0.699) (23.249,0.699) (23.249,0.699) (24.001,0.699) (24.001,0.699) (25.502,0.699) (25.502,0.699) (26.25,0.699) (26.25,0.699) (27.75,0.699) (27.75,0.699) (28.502,0.699) (28.502,0.699) (30,0.699) (30.75,0.699)
  rect 0.483x4.191 smd: 1(-31.5,-0.546) 2(-30.75,-0.546) 4(-29.25,-0.546) 7(-27,-0.546) 9(-25.5,-0.546) 10(-24.75,-0.546) 13(-22.5,-0.546) 16(-20.25,-0.546) 18(-18.75,-0.546) 19(-18,-0.546) 22(-15.75,-0.546) 25(-13.5,-0.546) 27(-12,-0.546) 28(-11.25,-0.546) 31(-9,-0.546) 34(-6.75,-0.546) 37(-4.5,-0.546) 40(-2.25,-0.546) 42(-0.75,-0.546) 43(0,-0.546) 46(2.25,-0.546) 49(4.5,-0.546) 52(6.75,-0.546) 55(9,-0.546) 57(10.5,-0.546) 58(11.25,-0.546) 61(13.5,-0.546) 64(15.75,-0.546) 67(18,-0.546) 70(20.25,-0.546) 72(21.75,-0.546) 73(22.5,-0.546) 76(24.75,-0.546) 79(27,-0.546) 82(29.25,-0.546) 84(30.75,-0.546) 85(31.5,-0.546) 86(31.5,-0.546) 89(29.25,-0.546) 92(27,-0.546) 95(24.75,-0.546) 98(22.5,-0.546) 101(20.25,-0.546) 104(18,-0.546) 107(15.75,-0.546) 110(13.5,-0.546) 113(11.25,-0.546) 116(9,-0.546) 119(6.75,-0.546) 122(4.5,-0.546) 125(2.25,-0.546) 128(0,-0.546) 131(-2.25,-0.546) 134(-4.5,-0.546) 137(-6.75,-0.546) 140(-9,-0.546) 143(-11.25,-0.546) 146(-13.5,-0.546) 149(-15.75,-0.546) 152(-18,-0.546) 155(-20.25,-0.546) 158(-22.5,-0.546) 161(-24.75,-0.546) 164(-27,-0.546) 170(-31.5,-0.546)
  rect 0.483x1.981 smd: 3(-29.999,-1.649) 83(30,-1.651)
  rect 0.483x3.023 smd: 5(-28.499,-1.131) 6(-27.749,-1.131) 8(-26.249,-1.131) 17(-19.502,-1.131) 26(-12.748,-1.129) 41(-1.5,-1.129) 56(9.749,-1.129) 71(21.001,-1.129) 165(-27.749,-1.131) 166(-28.499,-1.131) 167(-29.249,-1.131) 168(-29.999,-1.131) 169(-30.749,-1.131)
  rect 0.483x2.286 smd: 11(-24,-1.499) 12(-23.249,-1.499) 14(-21.748,-1.498) 15(-21,-1.498) 20(-17.248,-1.498) 21(-16.5,-1.498) 23(-15,-1.499) 24(-14.248,-1.499) 29(-10.5,-1.499) 30(-9.752,-1.499) 32(-8.248,-1.499) 33(-7.5,-1.499) 35(-6,-1.499) 36(-5.252,-1.499) 38(-3.752,-1.499) 39(-3,-1.499) 44(0.749,-1.499) 45(1.501,-1.499) 47(3.001,-1.499) 48(3.749,-1.499) 50(5.249,-1.499) 51(6.001,-1.499) 53(7.501,-1.499) 54(8.249,-1.499) 59(12.001,-1.499) 60(12.749,-1.499) 62(14.249,-1.499) 63(15.001,-1.499) 65(16.501,-1.499) 66(17.249,-1.499) 68(18.749,-1.499) 69(19.501,-1.499) 74(23.249,-1.499) 75(24.001,-1.499) 77(25.502,-1.499) 78(26.25,-1.499) 80(27.75,-1.499) 81(28.502,-1.499) 87(30.75,-1.499) 88(30,-1.499) 90(28.5,-1.499) 91(27.75,-1.499) 93(26.25,-1.499) 94(25.5,-1.499) 96(24,-1.499) 97(23.25,-1.499) 99(21.75,-1.499) 100(21,-1.499) 102(19.499,-1.499) 103(18.75,-1.499) 105(17.251,-1.498) 106(16.5,-1.498) 108(15.001,-1.499) 109(14.25,-1.499) 111(12.75,-1.499) 112(12,-1.499) 114(10.501,-1.499) 115(9.75,-1.499) 117(8.249,-1.498) 118(7.5,-1.498) 120(5.999,-1.499) 121(5.249,-1.499) 123(3.75,-1.499) 124(2.999,-1.499) 126(1.5,-1.499) 127(0.749,-1.499) 129(-0.752,-1.499) 130(-1.501,-1.499) 132(-3.002,-1.499) 133(-3.751,-1.499) 135(-5.25,-1.499) 136(-5.999,-1.499) 138(-7.5,-1.499) 139(-8.249,-1.499) 141(-9.75,-1.499) 142(-10.499,-1.499) 144(-12,-1.499) 145(-12.749,-1.499) 147(-14.25,-1.499) 148(-14.999,-1.499) 150(-16.499,-1.499) 151(-17.249,-1.499) 153(-18.748,-1.499) 154(-19.499,-1.499) 156(-20.999,-1.499) 157(-21.749,-1.499) 159(-23.249,-1.499) 160(-23.999,-1.499) 162(-25.499,-1.499) 163(-26.249,-1.499)
